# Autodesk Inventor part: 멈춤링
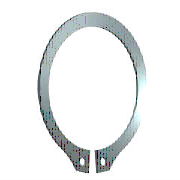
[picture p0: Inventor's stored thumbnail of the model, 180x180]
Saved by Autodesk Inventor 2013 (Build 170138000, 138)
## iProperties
IsCustomPart: 1
Created: 2012-02
Part Number: 멈춤링
Material: 강철, 연강
Description: 리테이닝 링(C형)
Document SubType Name: Modeling
Standard: KS B 1336
Designer: mduedu
Standards Organization: KS
Language: ko-KR
Size Designation: 20 x 1.2
Categories: <MemberInstance><Categories><Category DisplayName="샤프트 부품" InternalName="7f7aeb1f-a693-4053-b835-cee3144e0d98" Mnemonic="SHFT"><Category DisplayName="써클립" Inter
Density: 7.86 g/cm^3
Mass: 1.66546 g
Surface Area: 5.4075 cm^2
Volume: 0.211891 cm^3
Author: mduedu
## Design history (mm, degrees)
sketch "스케치1"
  geometry: L1 (-6, 0)-(6, 0) reference; L2 (0, 20.189)-(0, -80.536) reference; L3 (-48.09, 0)-(48.09, 0) reference; L4 (-0.5, -19.487)-(-0.5, -23.387); L5 (-0.5, -6.54)-(-0.5, -13.29); L6 (-2.795, 2.7)-(3.672, 2.7); L7 (0.5, -6.54)-(0.5, -13.29); L8 (0.5, -19.487)-(0.5, -23.387); C1 r 1 at (-2, -21.219); C2 r 1 at (2, -21.219); A1 r 9.5 centre (0, -10) between (0.5, -19.487) and (-0.5, -19.487); A2 r 12.025 centre (0, -9.325) between (5.071, -20.228) and (-5.071, -20.228); A3 r 13.396 centre (0, -10) between (-2.351, -23.188) and (-0.5, -23.387); A4 r 2 centre (-2, -21.219) between (-3.957, -21.631) and (-2.351, -23.188); A5 r 2 centre (-5.915, -22.042) between (-3.957, -21.631) and (-5.071, -20.228); A6 r 2 centre (5.915, -22.042) between (5.071, -20.228) and (3.957, -21.631); A7 r 2 centre (2, -21.219) between (2.351, -23.188) and (3.957, -21.631); A8 r 13.396 centre (0, -10) between (0.5, -23.387) and (2.351, -23.188)
  constraints: 16 point on circle, 12 end point, 10 centre point, 9 symmetric about line, 5 point on line, 4 tangent, 3 coincident, 2 horizontal, 1 perpendicular, 1 vertical, 5 other
  dimensions: "d0" = 19 diameter of A1 (= ND); "d1" = 3.9 distance of L4.end L4.start (= SRB2); "d6" = 0.5 distance between parallel lines of L2 L5 (= 0.25 x SD5); "d7" = 2.7 distance between parallel lines of L6 L3 (= SRB1); "d8" = 0.675 distance of A1.centre A2.centre (= 0.25 x SRB1); "d9" = 2 radius of A4 (= SD5); "d10" = 2 radius of A5 (= SD5); "d11" = 1.5 distance from line of L4 A4.centre (= 0.75 x SD5); "d12" = 2 diameter of C1 (= SD5); "d13" = 2 diameter of C2 (= SD5); "d14" = 10 distance from line of A1.centre L1 (= 0.5 x WD)
extrude "본체" new body sketch "스케치1" distance "d2" = 1.2 (= SD); taper "d3" = 0 deg
workaxis "Work Axis1"
workplane "Work Plane1"
body "Solid1"
other parameters: "SD" = 1.2 [user parameter; used in 1 equation term], "SRB1" = 2.7 [user parameter; used in 2 equation terms], "ND" = 19 [user parameter; used in 1 equation term], "SRB2" = 3.9 [user parameter; used in 1 equation term], "SD5" = 2 [user parameter; used in 6 equation terms], "d15" = 0, "d16" = 0, "d17" = 0, "d41" = 0, "d42" = 0, "SD3" = 18.5 [user parameter], "WDMAX" = 21 [user parameter]
